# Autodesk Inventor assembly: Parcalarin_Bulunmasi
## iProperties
Shininess: 0.0
Created: 2000-12
Part Number: Parcalarin_Bulunmasi
Checked By: PT
Document SubType Name: Assembly
Designer: Gary
Density: 0.0
Volumn: 0.0
Area: 0.0
PropertySet Name: Model Information
Control State: 0
Master: False
Checked Out: False
sheet: 200A
Title: Large Assembly Management
Author: Administrator
